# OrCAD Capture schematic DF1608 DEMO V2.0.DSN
size A4; title: DF1608 DEMO; rev: 2.0; note: Sean Chen
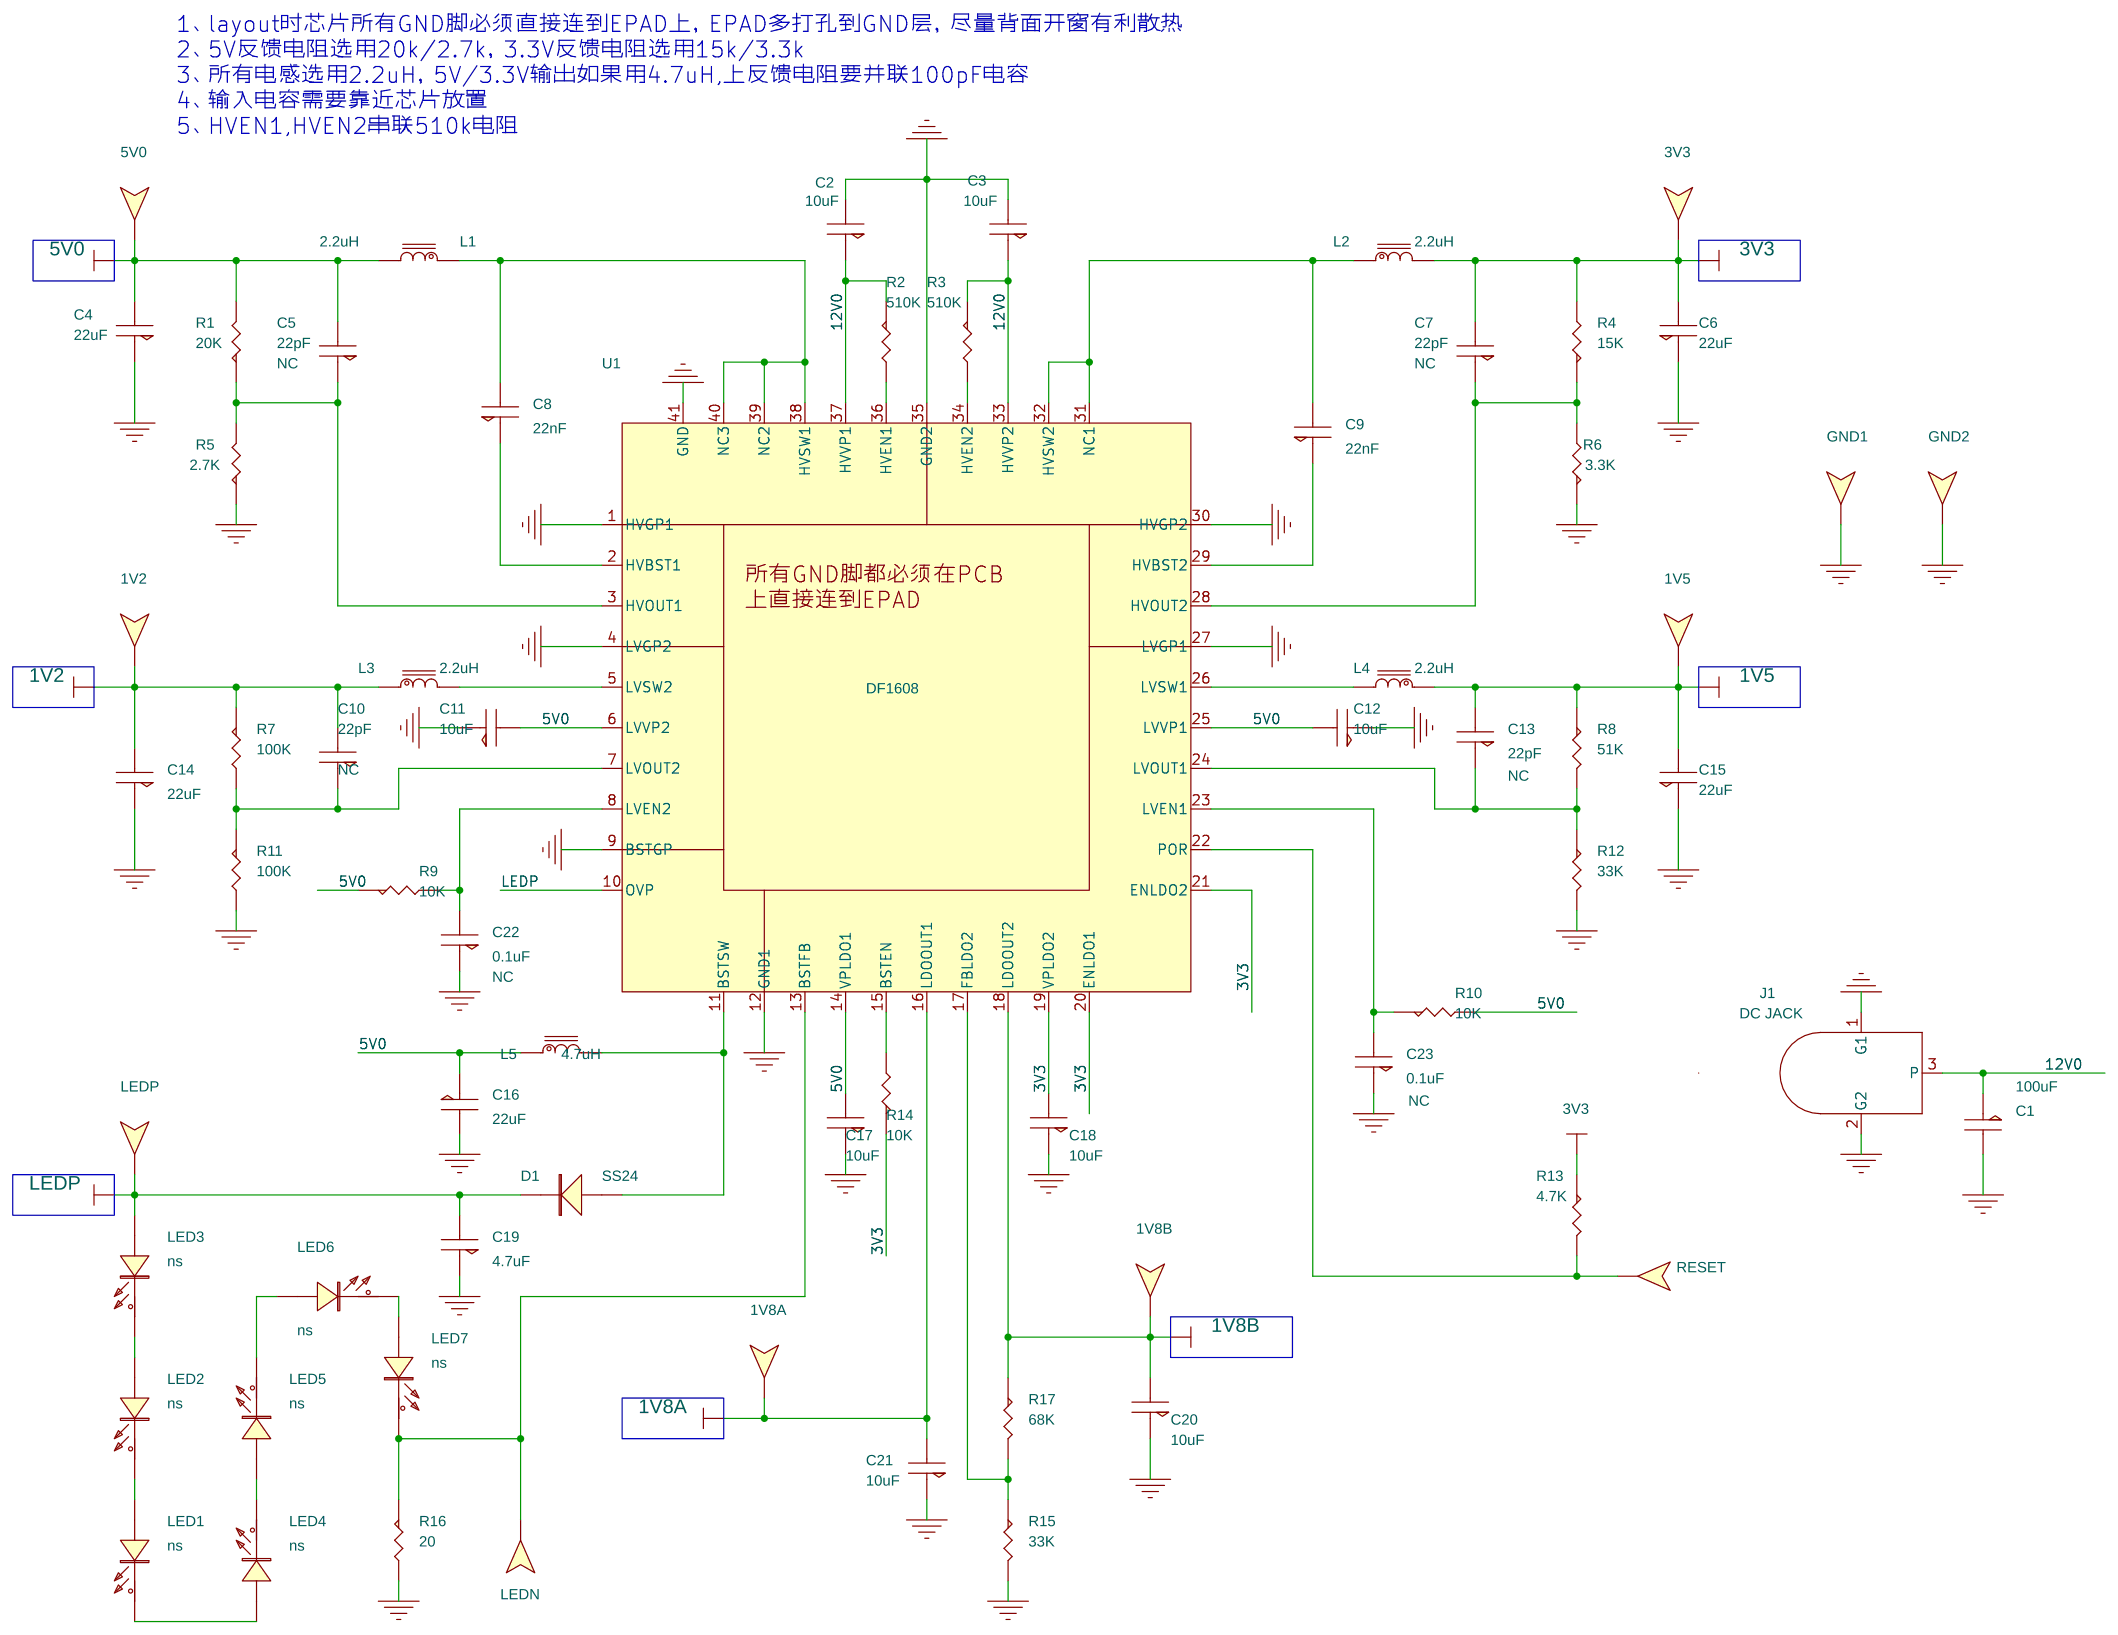
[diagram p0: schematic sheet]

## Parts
1V2  AS_TPWR  [TEST1_TH_PWR]
1V5  AS_TPWR  [TEST1_TH_PWR]
1V8A  AS_TPWR  [TEST1_TH_PWR]
1V8B  AS_TPWR  [TEST1_TH_PWR]
3V3  AS_TPWR  [TEST1_TH_PWR]
5V0  AS_TPWR  [TEST1_TH_PWR]
C1  100uF  [CE_RA_2R5_7]
C2  10uF  [R_0805]
C3  10uF  [R_0805]
C4  22uF  [R_0805]
C5  22pF  [R_0402]
C6  22uF  [R_0805]
C7  22pF  [R_0402]
C8  22nF  [R_0402]
C9  22nF  [R_0402]
C10  22pF  [R_0402]
C11  10uF  [R_0603]
C12  10uF  [R_0603]
C13  22pF  [R_0402]
C14  22uF  [R_0805]
C15  22uF  [R_0805]
C16  22uF  [R_0805]
C17  10uF  [R_0603]
C18  10uF  [R_0603]
C19  4.7uF  [R_0805]
C20  10uF  [R_0603]
C21  10uF  [R_0603]
C22  0.1uF  [R_0402]
C23  0.1uF  [R_0402]
D1  SS24  [DO_214AC_SMA]
GND1  AS_TPWR  [TEST1_TH_PWR]
GND2  AS_TPWR  [TEST1_TH_PWR]
J1  DC JACK  [PWR3_DC_TYPE1]
L1  2.2uH  [PL_4X4_TYPE3]
L2  2.2uH  [PL_4X4_TYPE3]
L3  2.2uH  [PL_4X4_TYPE3]
L4  2.2uH  [PL_4X4_TYPE3]
L5  4.7uH  [PL_4X4_TYPE3]
LED1  LED3020  [DO_214AC_SMA]
LED2  LED3020  [DO_214AC_SMA]
LED3  LED3020  [DO_214AC_SMA]
LED4  LED3020  [DO_214AC_SMA]
LED5  LED3020  [DO_214AC_SMA]
LED6  LED3020  [DO_214AC_SMA]
LED7  LED3020  [DO_214AC_SMA]
LEDN  AS_TPWR  [TEST1_TH_PWR]
LEDP  AS_TPWR  [TEST1_TH_PWR]
R1  20K  [R_0402]
R2  510K  [R_0402]
R3  510K  [R_0402]
R4  15K  [R_0402]
R5  2.7K  [R_0402]
R6  3.3K  [R_0402]
R7  100K  [R_0402]
R8  51K  [R_0402]
R9  10K  [R_0402]
R10  10K  [R_0402]
R11  100K  [R_0402]
R12  33K  [R_0402]
R13  4.7K  [R_0402]
R14  10K  [R_0603]
R15  33K  [R_0402]
R16  20  [R_0603]
R17  68K  [R_0402]
RESET  AS_TPWR  [TEST1_TH_PWR]
U1  DF1608  [QFN40_5X5]

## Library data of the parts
1V2 1V5 1V8A 1V8B 3V3 5V0 GND1 GND2 LEDN LEDP RESET = AS_TPWR
C1-C4 C6 C8 C9 C11 C12 C14-C21 = CAPNP
C5 C7 C10 C13 C22 C23 = CAPNP: Option: NC
D1 = DIODE
J1 = POWER_CON3
L1-L5 = INDUCTOR
LED1-LED7 = DIODE_LED: Board_option: PWR_BTN; option: ns
R1-R17 = R
U1 = DF1608

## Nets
1V2: 1V2.1(TP) C10.2 C14.2 L3.1 R7.1
1V5: 1V5.1(TP) C13.2 C15.2 L4.1 R8.1
1V8A: 1V8A.1(TP) C21.2 U1.16(LDOOUT1)
1V8B: 1V8B.1(TP) C20.2 R17.1 U1.18(LDOOUT2)
3V3: 3V3.1(TP) C6.2 C7.2 C18.2 L2.2 R4.2 R13.1 R14.1 U1.19(VPLDO2) U1.20(ENLDO1) U1.21(ENLDO2)
5V0: 5V0.1(TP) C4.2 C5.2 C11.2 C12.2 C16.1 C17.2 L1.2 L5.1 R1.2 R9.1 R10.2 U1.6(LVVP2) U1.14(VPLDO1) U1.25(LVVP1)
12V0: C1.1 C2.1 C3.1 J1.3(P) R2.1 R3.1 U1.33(HVVP2) U1.37(HVVP1)
GND: C1.2 C2.2 C3.2 C4.1 C6.1 C11.1 C12.1 C14.1 C15.1 C16.2 C17.1 C18.1 C19.1 C20.1 C21.1 C22.1 C23.1 GND1.1(TP) GND2.1(TP) J1.1(G1) J1.2(G2) R5.1 R6.1 R11.2 R12.2 R15.2 R16.2 U1.1(HVGP1) U1.4(LVGP2) U1.9(BSTGP) U1.12(GND1) U1.27(LVGP1) U1.30(HVGP2) U1.35(GND2) U1.41(GND)
LEDP: C19.2 D1.2(C) LED3.1(ANODE) LEDP.1(TP) U1.10(OVP)
N46671: C10.1 R7.2 R11.1 U1.7(LVOUT2)
N47440: D1.1(A) L5.2 U1.11(BSTSW)
N47975: R13.2 RESET.1(TP) U1.22(POR)
N48232: C13.1 R8.2 R12.1 U1.24(LVOUT1)
N48310: L4.2 U1.26(LVSW1)
N93462: C8.2 L1.1 U1.38(HVSW1) U1.39(NC2) U1.40(NC3)
N93473: C9.2 L2.1 U1.31(NC1) U1.32(HVSW2)
N94017: C5.1 R1.1 R5.2 U1.3(HVOUT1)
N94037: C7.1 R4.1 R6.2 U1.28(HVOUT2)
N97846: L3.2 U1.5(LVSW2)
N124673: R2.2 U1.36(HVEN1)
N124758: R3.2 U1.34(HVEN2)
N126504: R14.2 U1.15(BSTEN)
N133824: C22.2 R9.2 U1.8(LVEN2)
N134039: C23.2 R10.1 U1.23(LVEN1)
N147245: C8.1 U1.2(HVBST1)
N147286: C9.1 U1.29(HVBST2)
N150273: LED2.1(ANODE) LED3.2(CATHODE)
N150277: LED1.1(ANODE) LED2.2(CATHODE)
N150281: LED1.2(CATHODE) LED4.1(ANODE)
N150291: LED4.2(CATHODE) LED5.1(ANODE)
N150299: LED6.2(CATHODE) LED7.1(ANODE)
N150309: LED7.2(CATHODE) LEDN.1(TP) R16.1 U1.13(BSTFB)
N150430: LED5.2(CATHODE) LED6.1(ANODE)
N151242: R15.1 R17.2 U1.17(FBLDO2)

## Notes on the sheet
- 1、layout时芯片所有GND脚必须直接连到EPAD上，EPAD多打孔到GND层，尽量背面开窗有利散热
  2、5V反馈电阻选用20k/2.7k，3.3V反馈电阻选用15k/3.3k
  3、所有电感选用2.2uH，5V/3.3V输出如果用4.7uH,上反馈电阻要并联100pF电容
  4、输入电容需要靠近芯片放置
  5、HVEN1,HVEN2串联510k电阻
